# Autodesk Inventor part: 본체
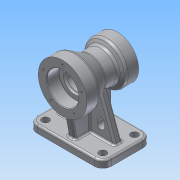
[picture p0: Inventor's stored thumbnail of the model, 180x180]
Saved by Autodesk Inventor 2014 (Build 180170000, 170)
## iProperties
Created: 2015-08
Part Number: 본체
Material: 알루미늄 6061
Document SubType Name: Modeling
Designer: SDA24
Density: 2.71 g/cm^3
Appearance: 알루미늄 - 평지
Mass: 1067.86 g
Surface Area: 754.722 cm^2
Volume: 394.043 cm^3
Author: SDA24
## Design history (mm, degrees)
sketch "스케치2"
  geometry: L1 (-45, 0)-(45, 0); L2 (-45, 0)-(-45, 35); L3 (-45, 35)-(-25, 35); L4 (-25, 35)-(-19.804, 26); L5 (45, 0)-(45, 40); L6 (45, 40)-(25, 40); L7 (25, 40)-(0.751, 26); L8 (0.751, 26)-(-19.804, 26); 2 further points
  constraints: 16 end point, 5 perpendicular, 2 horizontal, 1 coincident, 1 midpoint
  dimensions: "d1" = 90 distance of L1.start L1.end; "d2" = 35 distance of L1.start L2.end; "d3" = 20 distance of L2.end L3.end; "d6" = 40 distance of L1.end L5.end; "d7" = 26 distance between parallel lines of L1 L8; "d9" = 20 distance of L5.end L6.end; "d10" = 60 deg angle of L4 L8
revolve "회전1" sketch "스케치2" stored, may be unused: angle "d11" = 90 deg
sketch "스케치5"
  geometry: C1 r 35 at (0, 0) reference; C2 r 20 at (0, 0)
  constraints: 1 centre point, 1 coincident
  dimensions: "d16" = 40 diameter of C2
fillet "모깎기1" dims "d24" = 5
node "작업 평면2"
sketch "스케치14"
  geometry: L1 (-40, -61)-(40, -61); L2 (40, -61)-(40, 61); L3 (40, 61)-(-40, 61); L4 (-40, 61)-(-40, -61); L5 (-40, -61)-(40, 61); L6 (40, -61)-(-40, 61); 1 further point
  constraints: 12 end point, 2 midpoint, 2 parallel, 1 horizontal, 1 perpendicular
  dimensions: "d52" = 80 distance of L3.end L2.end; "d53" = 122 distance of L2.end L1.end
extrude "돌출9" join sketch "스케치14" distance "d54" = 12; taper "d55" = 0 deg
sketch "스케치16"
  geometry: L1 (-36.7, -40)-(-30, -78); L2 (-1.912, -26.67)-(-23.84, -39.33) reference; L3 (16.917, -26)-(0.588, -26) reference; L4 (23.557, -32.5)-(21.247, -28.5) reference; L5 (40, -78)-(-40, -78) reference; L6 (30, -35)-(30, -78); L7 (-36.7, -40)-(-26.34, -40); L8 (27.887, -35)-(30, -35); L9 (-30, -78)-(30, -78); A1 r 5 centre (-26.34, -35) between (-26.34, -40) and (-23.84, -39.33) reference; A2 r 5 centre (0.588, -31) between (0.588, -26) and (-1.912, -26.67) reference; A3 r 5 centre (16.917, -31) between (21.247, -28.5) and (16.917, -26) reference; A4 r 5 centre (27.887, -30) between (23.557, -32.5) and (27.887, -35) reference; 1 further point
  constraints: 10 end point, 2 point on line, 1 collinear, 1 parallel, 1 perpendicular, 1 tangent, 1 vertical
  dimensions: "d59" = 80 deg angle of L5 L1; "d60" = 10 distance of L1.end L5.end; "d61" = 10 distance of L5.start L6.end
extrude "돌출10" join sketch "스케치16" stored distance "d62" = 12; taper "d63" = 0 deg
node "작업 평면3"
sketch "스케치18"
  geometry: 1 further point
sketch "스케치22" dims "d84" = 66
  geometry: L1 (0, 0)-(-33, 0); C1 r 40 at (0, 0) reference
  constraints: 2 end point, 1 coincident, 1 horizontal, 1 horizontal alignment, 2 other
hole "구멍1" sketch "스케치22" at (-33, 0) diameter "d85" = 3.242; stored, may be unused: countersink angle "d89" = 90 deg, drill point angle "d91" = 118 deg; dims "d86" = 10, "d87" = 4, "d88" = 2, "d90" = 13
sketch "스케치23" dims "d95" = 54
  geometry: L1 (0, 0)-(27, 0); C1 r 35 at (0, 0) reference
  constraints: 2 end point, 1 coincident, 1 horizontal, 1 horizontal alignment, 2 other
hole "구멍2" sketch "스케치23" at (27, 0) diameter "d96" = 3.242; stored, may be unused: countersink angle "d100" = 90 deg, drill point angle "d102" = 118 deg; dims "d97" = 10, "d98" = 4, "d99" = 2, "d101" = 13
node "작업 평면5"
sketch "스케치24"
  geometry: L1 (-12, 122)-(-12, 0) reference; L2 (-12, 14)-(-77.902, 37.986); L3 (-12, 108)-(-77.902, 84.014); L4 (-12, 14)-(-12, 108); A1 r 26 centre (-90, 61) between (-64, 61) and (-77.902, 37.986) reference; A2 r 26 centre (-90, 61) between (-77.902, 37.986) and (-77.902, 84.014); 1 further point
  constraints: 6 end point, 5 point on circle, 2 point on line, 1 centre point, 1 collinear
  dimensions: "d112" = 70 deg angle of L4 L2; "d113" = 70 deg angle of L1 L3; "d114" = 47 vertical distance of L2.start point (-90, 61); "d115" = 47 vertical distance of L3.start point (-90, 61)
extrude "돌출13" join sketch "스케치24" stored distance "d116" = 12; taper "d117" = 0 deg
sketch "스케치25"
  geometry: L1 (-40, -78)-(40, -78) reference; 3 further points
  constraints: 1 other
  dimensions: "d118" = 24 distance from line of point (-14, -54) L1; "d119" = 16 horizontal distance of point (-14, -54) point (-30, -78)
feature "엠보싱1" sketch "스케치25" dims "d1" = 90, "d120" = 0.5, "d121" = 0
sketch "스케치26"
  geometry: L1 (-12, 122)-(-12, 0) reference; L2 (-36.002, 31)-(-30, 31); L3 (-30, 43)-(-36.002, 43); A1 r 29.03 centre (-90, 61) between (-60.97, 61) and (-74.207, 85.359) reference; A2 r 6 centre (-30, 37) between (-30, 31) and (-30, 43); A3 r 6 centre (-36.002, 37) between (-36.002, 43) and (-36.002, 31)
  constraints: 4 end point, 4 point on circle, 2 centre point, 2 tangent, 1 horizontal alignment, 1 parallel
  dimensions: "d132" = 6 radius of A3; "d133" = 6 radius of A2; "d134" = 24 vertical distance of A1.centre A2.centre; "d135" = 18 distance from line of A2.centre L1; "d137" = 12 distance between parallel lines of L3 L2; "d138" = 6.00211 distance of A2.centre A3.centre
extrude "돌출14" cut sketch "스케치26" stored distance "d139" = 12; taper "d140" = 0 deg
fillet "모깎기2" dims "d141" = 14
sketch "스케치28"
  geometry: L1 (26, 47)-(-26, 47); L2 (-26, 47)-(-26, -47); L3 (-26, -47)-(26, -47); L4 (26, -47)-(26, 47); L5 (26, 47)-(-26, -47); L6 (-26, 47)-(26, -47); A1 r 14 centre (26, -47) between (26, -61) and (40, -47) reference; A2 r 14 centre (26, 47) between (40, 47) and (26, 61) reference; A3 r 14 centre (-26, 47) between (-26, 61) and (-40, 47) reference; A4 r 14 centre (-26, -47) between (-40, -47) and (-26, -61) reference; 1 further point
  constraints: 12 end point, 2 midpoint, 2 parallel, 1 horizontal, 1 perpendicular
  dimensions: "d142" = 52 distance of L3.end L2.end; "d143" = 94 distance of L1.end L2.end
hole "구멍3" sketch "스케치28" at (-26, -47), (26, -47), (26, 47), (-26, 47) diameter "d144" = 12; stored, may be unused: countersink angle "d148" = 90 deg, drill point angle "d150" = 0 deg; dims "d145" = 12, "d146" = 4, "d147" = 2, "d149" = 13
fillet "모깎기3" dims "d151" = 3
fillet "모깎기4" dims "d152" = 3
sketch "스케치29"
  geometry: C1 r 40 at (0, 0) reference; C2 r 26 at (0, 0)
  constraints: 1 centre point, 1 coincident
  dimensions: "d156" = 52 diameter of C2
extrude "돌출15" cut sketch "스케치29" distance "d157" = 20; taper "d158" = 0 deg
sketch "스케치30"
  geometry: C1 r 26 at (0, 0) reference; C2 r 19 at (0, 0)
  constraints: 1 centre point, 1 coincident
  dimensions: "d159" = 38 diameter of C2
extrude "돌출16" cut sketch "스케치30" distance "d160" = 3; taper "d161" = 0 deg
fillet "모깎기8" dims "d162" = 3
extrude "돌출17" cut sketch "스케치5" distance "d163" = 17; taper "d164" = 0 deg
sketch "스케치31"
  geometry: C1 r 20 at (0, 0) reference; C2 r 16 at (0, 0)
  constraints: 1 centre point, 1 coincident
  dimensions: "d165" = 32 diameter of C2
extrude "돌출18" cut sketch "스케치31" stored distance "d166" = 17; taper "d167" = 0 deg
fillet "모깎기9" dims "d168" = 0.3
chamfer "모따기1" distance "d169" = 1; stored, may be unused: second distance "d170" = 2, angle "d171" = 45 deg
node "솔리드1"
mirror "대칭1"
pattern_circular "원형 패턴3" dims angle "d173" = 360 deg
pattern_circular "원형 패턴4" dims angle "d176" = 360 deg
other parameters: "d76" = -45
